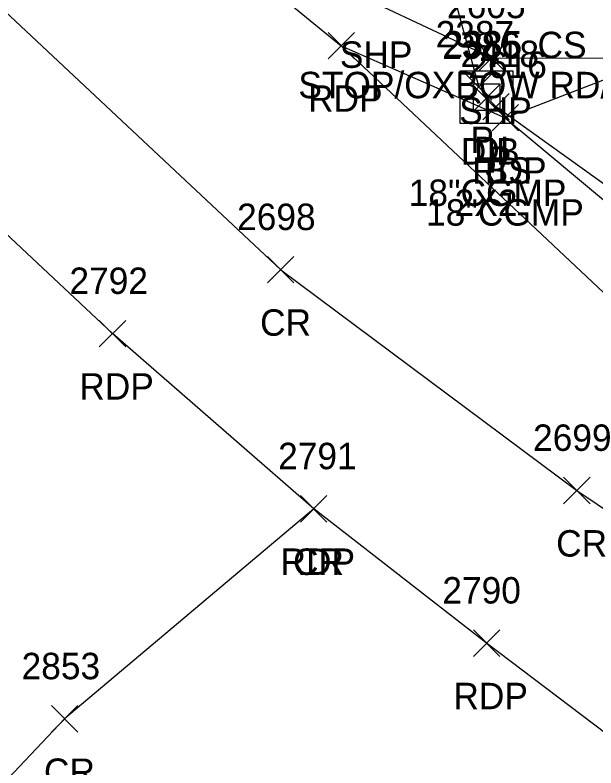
# Model space of a CAD drawing. Extents: x 1504228 to 1506103, y 437717 to 440106.
# Drawn here: x 1505287 to 1505331, y 438079.5 to 438136.5 of the extents above; entities that cross this region are included whole.
import ezdxf

# ---------------------------------------------------------------- set-up
doc = ezdxf.new("R2010")
doc.units = 0
for name, color, linetype in [('D_A', 7, 'Continuous'), ('D_C', 7, 'Continuous'), ('D_I', 7, 'Continuous'), ('D_TIC', 7, 'Continuous'), ('DCP', 7, 'Continuous'), ('DS', 7, 'Continuous'), ('L_A', 7, 'Continuous'), ('L_I', 7, 'Continuous'), ('L_TIC', 7, 'Continuous'), ('LELB', 7, 'Continuous'), ('P_A', 7, 'Continuous'), ('P_I', 7, 'Continuous'), ('P_TIC', 7, 'Continuous'), ('PET', 7, 'Continuous'), ('PRC', 7, 'Continuous'), ('PSP', 7, 'Continuous'), ('S_C', 7, 'Continuous')]:
    doc.layers.add(name, color=color, linetype=linetype)

msp = doc.modelspace()

# ---------------------------------------------------------------- linework, layer by layer
at = {"layer": 'D_TIC'}
for points in [[(1505321.088, 438130.045), (1505323.088, 438132.045)], [(1505323.088, 438130.045), (1505321.088, 438132.045)], [(1505321.633, 438129.18), (1505323.633, 438131.18)], [(1505323.633, 438129.18), (1505321.633, 438131.18)], [(1505322.404, 438128.556), (1505324.404, 438130.556)], [(1505324.404, 438128.556), (1505322.404, 438130.556)]]:
    msp.add_lwpolyline(points, dxfattribs=at)
at = {"layer": 'DCP'}
for points in [[(1505306.265, 438188.781), (1505322.088, 438131.045)], [(1505359.818, 438103.471), (1505323.404, 438129.556)]]:
    msp.add_lwpolyline(points, dxfattribs=at)
at = {"layer": 'DS'}
for p, q in [((1505320.684, 438132.282), (1505324.684, 438132.282)), ((1505320.684, 438128.282), (1505320.684, 438132.282)), ((1505324.684, 438132.282), (1505324.684, 438128.282)), ((1505321.684, 438129.282), (1505321.684, 438131.282)), ((1505321.684, 438131.282), (1505323.684, 438131.282)), ((1505323.684, 438131.282), (1505323.684, 438129.282)), ((1505322.689, 438130.284), (1505322.689, 438130.284)), ((1505322.689, 438130.284), (1505322.689, 438130.284)), ((1505323.684, 438129.282), (1505321.684, 438129.282)), ((1505324.684, 438128.282), (1505320.684, 438128.282))]:
    msp.add_line(p, q, dxfattribs=at)
at = {"layer": 'L_TIC'}
for points in [[(1505323.098, 438127.725), (1505325.098, 438129.725)], [(1505325.098, 438127.725), (1505323.098, 438129.725)]]:
    msp.add_lwpolyline(points, dxfattribs=at)
at = {"layer": 'LELB'}
msp.add_lwpolyline([(1505324.098, 438128.725), (1505341.256, 438114.415), (1505366.164, 438099.366)], dxfattribs=at)
at = {"layer": 'P_TIC'}
for points in [[(1505310.676, 438133.175), (1505312.676, 438135.175)], [(1505312.676, 438133.175), (1505310.676, 438135.175)], [(1505310.676, 438133.175), (1505312.676, 438135.175)], [(1505312.676, 438133.175), (1505310.676, 438135.175)], [(1505322.075, 438132.257), (1505324.075, 438134.257)], [(1505324.075, 438132.257), (1505322.075, 438134.257)], [(1505323.098, 438127.725), (1505325.098, 438129.725)], [(1505325.098, 438127.725), (1505323.098, 438129.725)], [(1505306.093, 438116.221), (1505308.093, 438118.221)], [(1505308.093, 438116.221), (1505306.093, 438118.221)], [(1505293.343, 438111.385), (1505295.343, 438113.385)], [(1505295.343, 438111.385), (1505293.343, 438113.385)], [(1505328.521, 438099.507), (1505330.521, 438101.507)], [(1505330.521, 438099.507), (1505328.521, 438101.507)], [(1505308.586, 438098.121), (1505310.586, 438100.121)], [(1505310.586, 438098.121), (1505308.586, 438100.121)], [(1505308.586, 438098.121), (1505310.586, 438100.121)], [(1505310.586, 438098.121), (1505308.586, 438100.121)], [(1505321.682, 438087.954), (1505323.682, 438089.954)], [(1505323.682, 438087.954), (1505321.682, 438089.954)], [(1505289.718, 438082.224), (1505291.718, 438084.224)], [(1505291.718, 438082.224), (1505289.718, 438084.224)]]:
    msp.add_lwpolyline(points, dxfattribs=at)
at = {"layer": 'PET'}
for points in [[(1505311.676, 438134.175), (1505324.098, 438128.725), (1505335.82, 438133.23), (1505344.252, 438137.011), (1505351.761, 438143.58), (1505369.207, 438162.724), (1505390.677, 438190.218), (1505407.619, 438213.727), (1505418.189, 438229.936), (1505438.053, 438265.664)], [(1505219.541, 438139.332), (1505229.478, 438143.453), (1505236.137, 438147.016), (1505243.065, 438149.521), (1505252.019, 438153.342), (1505263.781, 438158.664), (1505277.038, 438164.677), (1505295.889, 438147.093), (1505311.676, 438134.175), (1505338.301, 438109.134), (1505363.246, 438092.977), (1505381.83, 438081.07), (1505419.293, 438061.963), (1505441.952, 438049.929), (1505474.016, 438032.73)], [(1505461.721, 438009.735), (1505401.749, 438041.504), (1505373.571, 438057.173), (1505346.175, 438071.197), (1505322.682, 438088.954), (1505309.586, 438099.121), (1505294.343, 438112.385), (1505276.045, 438129.534)]]:
    msp.add_lwpolyline(points, dxfattribs=at)
at = {"layer": 'PRC'}
for points in [[(1505263.781, 438158.664), (1505284.158, 438138.68), (1505307.093, 438117.221), (1505329.521, 438100.507), (1505353.091, 438084.687), (1505386.556, 438065.64), (1505412.799, 438050.856), (1505435.687, 438038.531), (1505467.608, 438021.56)], [(1505309.586, 438099.121), (1505290.718, 438083.224), (1505277.049, 438068.798), (1505267.181, 438054.638), (1505262.335, 438042.731), (1505260.454, 438023.846)]]:
    msp.add_lwpolyline(points, dxfattribs=at)
at = {"layer": 'PSP'}
msp.add_lwpolyline([(1505298.089, 438149.32), (1505314.034, 438137.497), (1505323.075, 438133.257), (1505335.82, 438133.23)], dxfattribs=at)

# ---------------------------------------------------------------- texts
at = {"layer": 'D_A'}
for s, p in [('P', (1505321.466, 438126.045)), ('DIB', (1505320.735, 438125.18)), ('DI', (1505321.744, 438125.284)), ('P', (1505322.782, 438124.556))]:
    msp.add_text(s, height=2, dxfattribs=at).set_placement(p)
at = {"layer": 'D_C'}
for s, p in [('18"CGMP', (1505316.788, 438122.045)), ('2X2', (1505320.264, 438121.284)), ('18"CGMP', (1505318.105, 438120.556))]:
    msp.add_text(s, height=2, dxfattribs=at).set_placement(p)
at = {"layer": 'D_I'}
for s, p in [('2387', (1505318.828, 438134.045)), ('2386', (1505319.318, 438133.18)), ('2385', (1505319.429, 438133.284)), ('2418', (1505320.711, 438132.556))]:
    msp.add_text(s, height=2, dxfattribs=at).set_placement(p)
at = {"layer": 'L_A'}
for s, p in [('CS', (1505326.546, 438133.232)), ('BS', (1505322.539, 438123.725))]:
    msp.add_text(s, height=2, dxfattribs=at).set_placement(p)
at = {"layer": 'L_I'}
msp.add_text('2616', height=2, dxfattribs=at).set_placement((1505321.302, 438131.725))
at = {"layer": 'P_A'}
for s, p in [('SHP', (1505311.569, 438132.497)), ('RDP', (1505309.164, 438129.175)), ('RDP', (1505309.164, 438129.175)), ('SHP', (1505320.61, 438128.257)), ('RDP', (1505321.586, 438123.725)), ('CR', (1505305.526, 438112.221)), ('RDP', (1505291.831, 438107.385)), ('CR', (1505327.955, 438095.507)), ('RDP', (1505307.075, 438094.121)), ('CR', (1505308.019, 438094.121)), ('RDP', (1505320.17, 438083.954)), ('CR', (1505289.151, 438078.224))]:
    msp.add_text(s, height=2, dxfattribs=at).set_placement(p)
at = {"layer": 'P_I'}
for s, p in [('2605', (1505319.689, 438136.257)), ('2616', (1505321.302, 438131.725)), ('2698', (1505303.785, 438120.221)), ('2792', (1505291.083, 438115.385)), ('2699', (1505326.206, 438103.507)), ('2791', (1505306.893, 438102.121)), ('2791', (1505306.893, 438102.121)), ('2790', (1505319.335, 438091.954)), ('2853', (1505287.458, 438086.224))]:
    msp.add_text(s, height=2, dxfattribs=at).set_placement(p)
at = {"layer": 'S_C'}
msp.add_text('STOP/OXBOW RD/MM0070/1116/0281', height=2, dxfattribs=at).set_placement((1505308.425, 438130.197))

doc.saveas('drawing.dxf')
